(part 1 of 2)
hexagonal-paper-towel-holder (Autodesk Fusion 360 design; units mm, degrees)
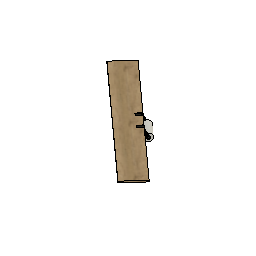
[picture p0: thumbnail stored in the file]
sketch "Sketch1" plane through (0, 0, 0) normal (0, 0, 1) x axis (1, 0, 0)
  line L1 (37.5278, 105) -> (-17.3205, 10)
  line L2 (90, 10) -> (-17.3205, 10)
  line L3 (117.5278, 105) -> (37.5278, 105)
  line L4 (15.1099, -13.1031) -> (117.5278, 105)
  line L5 (44.2265, 70) -> (47.1132, 75)
  line L6 (47.1132, 65) -> (44.2265, 70)
  line L7 (52.8868, 65) -> (47.1132, 65)
  line L8 (55.7735, 70) -> (52.8868, 65)
  line L9 (52.8868, 75) -> (55.7735, 70)
  line L10 (47.1132, 75) -> (52.8868, 75)
  line L11 (54.3301, 72.5) -> (50, 70)
  line L12 (54.3301, 67.5) -> (50, 70)
  line L13 (-19.6944, 13.5714) -> (-22.5812, 18.5714)
  line L14 (-13.9209, 13.5714) -> (-19.6944, 13.5714)
  line L15 (-11.0342, 18.5714) -> (-13.9209, 13.5714)
  line L16 (-13.9209, 23.5714) -> (-11.0342, 18.5714)
  line L17 (-22.5812, 18.5714) -> (-19.6944, 23.5714)
  line L18 (-19.6944, 23.5714) -> (-13.9209, 23.5714)
  line L19 (-8.5598, 20) -> (-11.4466, 25)
  line L20 (-2.7863, 20) -> (-8.5598, 20)
  line L21 (0.1004, 25) -> (-2.7863, 20)
  line L22 (-2.7863, 30) -> (0.1004, 25)
  line L23 (-11.4466, 25) -> (-8.5598, 30)
  line L24 (-8.5598, 30) -> (-2.7863, 30)
  line L25 (2.5748, 13.5714) -> (-0.312, 18.5714)
  line L26 (8.3483, 13.5714) -> (2.5748, 13.5714)
  line L27 (11.2351, 18.5714) -> (8.3483, 13.5714)
  line L28 (8.3483, 23.5714) -> (11.2351, 18.5714)
  line L29 (-0.312, 18.5714) -> (2.5748, 23.5714)
  line L30 (2.5748, 23.5714) -> (8.3483, 23.5714)
  line L31 (-8.5598, 32.8571) -> (-11.4466, 37.8571)
  line L32 (-2.7863, 32.8571) -> (-8.5598, 32.8571)
  line L33 (0.1004, 37.8571) -> (-2.7863, 32.8571)
  line L34 (-2.7863, 42.8571) -> (0.1004, 37.8571)
  line L35 (-11.4466, 37.8571) -> (-8.5598, 42.8571)
  line L36 (-8.5598, 42.8571) -> (-2.7863, 42.8571)
  line L37 (2.5748, 26.4286) -> (-0.312, 31.4286)
  line L38 (8.3483, 26.4286) -> (2.5748, 26.4286)
  line L39 (11.2351, 31.4286) -> (8.3483, 26.4286)
  line L40 (8.3483, 36.4286) -> (11.2351, 31.4286)
  line L41 (-0.312, 31.4286) -> (2.5748, 36.4286)
  line L42 (2.5748, 36.4286) -> (8.3483, 36.4286)
  line L43 (13.7094, 20) -> (10.8227, 25)
  line L44 (19.4829, 20) -> (13.7094, 20)
  line L45 (22.3697, 25) -> (19.4829, 20)
  line L46 (19.4829, 30) -> (22.3697, 25)
  line L47 (10.8227, 25) -> (13.7094, 30)
  line L48 (13.7094, 30) -> (19.4829, 30)
  line L49 (2.5748, 39.2857) -> (-0.312, 44.2857)
  line L50 (8.3483, 39.2857) -> (2.5748, 39.2857)
  line L51 (11.2351, 44.2857) -> (8.3483, 39.2857)
  line L52 (8.3483, 49.2857) -> (11.2351, 44.2857)
  line L53 (-0.312, 44.2857) -> (2.5748, 49.2857)
  line L54 (2.5748, 49.2857) -> (8.3483, 49.2857)
  line L55 (13.7094, 32.8571) -> (10.8227, 37.8571)
  line L56 (19.4829, 32.8571) -> (13.7094, 32.8571)
  line L57 (22.3697, 37.8571) -> (19.4829, 32.8571)
  line L58 (19.4829, 42.8571) -> (22.3697, 37.8571)
  line L59 (10.8227, 37.8571) -> (13.7094, 42.8571)
  line L60 (13.7094, 42.8571) -> (19.4829, 42.8571)
  line L61 (24.844, 26.4286) -> (21.9573, 31.4286)
  line L62 (30.6175, 26.4286) -> (24.844, 26.4286)
  line L63 (33.5043, 31.4286) -> (30.6175, 26.4286)
  line L64 (30.6175, 36.4286) -> (33.5043, 31.4286)
  line L65 (21.9573, 31.4286) -> (24.844, 36.4286)
  line L66 (24.844, 36.4286) -> (30.6175, 36.4286)
  line L67 (2.5748, 52.1429) -> (-0.312, 57.1429)
  line L68 (8.3483, 52.1429) -> (2.5748, 52.1429)
  line L69 (11.2351, 57.1429) -> (8.3483, 52.1429)
  line L70 (8.3483, 62.1429) -> (11.2351, 57.1429)
  line L71 (-0.312, 57.1429) -> (2.5748, 62.1429)
  line L72 (2.5748, 62.1429) -> (8.3483, 62.1429)
  line L73 (13.7094, 45.7143) -> (10.8227, 50.7143)
  line L74 (19.4829, 45.7143) -> (13.7094, 45.7143)
  line L75 (22.3697, 50.7143) -> (19.4829, 45.7143)
  line L76 (19.4829, 55.7143) -> (22.3697, 50.7143)
  line L77 (10.8227, 50.7143) -> (13.7094, 55.7143)
  line L78 (13.7094, 55.7143) -> (19.4829, 55.7143)
  line L79 (24.844, 39.2857) -> (21.9573, 44.2857)
  line L80 (30.6175, 39.2857) -> (24.844, 39.2857)
  line L81 (33.5043, 44.2857) -> (30.6175, 39.2857)
  line L82 (30.6175, 49.2857) -> (33.5043, 44.2857)
  line L83 (21.9573, 44.2857) -> (24.844, 49.2857)
  line L84 (24.844, 49.2857) -> (30.6175, 49.2857)
  line L85 (35.9786, 32.8571) -> (33.0919, 37.8571)
  line L86 (41.7521, 32.8571) -> (35.9786, 32.8571)
  line L87 (44.6389, 37.8571) -> (41.7521, 32.8571)
  line L88 (41.7521, 42.8571) -> (44.6389, 37.8571)
  line L89 (33.0919, 37.8571) -> (35.9786, 42.8571)
  line L90 (35.9786, 42.8571) -> (41.7521, 42.8571)
  line L91 (13.7094, 58.5714) -> (10.8227, 63.5714)
  line L92 (19.4829, 58.5714) -> (13.7094, 58.5714)
  line L93 (22.3697, 63.5714) -> (19.4829, 58.5714)
  line L94 (19.4829, 68.5714) -> (22.3697, 63.5714)
  line L95 (10.8227, 63.5714) -> (13.7094, 68.5714)
  line L96 (13.7094, 68.5714) -> (19.4829, 68.5714)
  line L97 (24.844, 52.1429) -> (21.9573, 57.1429)
  line L98 (30.6175, 52.1429) -> (24.844, 52.1429)
  line L99 (33.5043, 57.1429) -> (30.6175, 52.1429)
  line L100 (30.6175, 62.1429) -> (33.5043, 57.1429)
  line L101 (21.9573, 57.1429) -> (24.844, 62.1429)
  line L102 (24.844, 62.1429) -> (30.6175, 62.1429)
  line L103 (35.9786, 45.7143) -> (33.0919, 50.7143)
  line L104 (41.7521, 45.7143) -> (35.9786, 45.7143)
  line L105 (44.6389, 50.7143) -> (41.7521, 45.7143)
  line L106 (41.7521, 55.7143) -> (44.6389, 50.7143)
  line L107 (33.0919, 50.7143) -> (35.9786, 55.7143)
  line L108 (35.9786, 55.7143) -> (41.7521, 55.7143)
  line L109 (47.1132, 39.2857) -> (44.2265, 44.2857)
  line L110 (52.8868, 39.2857) -> (47.1132, 39.2857)
  line L111 (55.7735, 44.2857) -> (52.8868, 39.2857)
  line L112 (52.8868, 49.2857) -> (55.7735, 44.2857)
  line L113 (44.2265, 44.2857) -> (47.1132, 49.2857)
  line L114 (47.1132, 49.2857) -> (52.8868, 49.2857)
  line L115 (13.7094, 71.4286) -> (10.8227, 76.4286)
  line L116 (19.4829, 71.4286) -> (13.7094, 71.4286)
  line L117 (22.3697, 76.4286) -> (19.4829, 71.4286)
  line L118 (19.4829, 81.4286) -> (22.3697, 76.4286)
  line L119 (10.8227, 76.4286) -> (13.7094, 81.4286)
  line L120 (13.7094, 81.4286) -> (19.4829, 81.4286)
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  point P1 (0, 0)
  point P2 (0, 0)
  point P8 (50, 70)
  point P15 (50, 70)
  point P16 (50, 70)
  point P17 (54.3301, 72.5)
  point P18 (50, 70)
  point P19 (54.3301, 67.5)
  point P384 (0, 0)
  point P5 (37.5278, 105)
  point P6 (117.5278, 105)
  coincident P1 P2
  horizontal L2
  coincident P8 P15
  coincident P15 P16
  midpoint L9 P17
  coincident P8 P18
  midpoint L8 P19
  coincident P1 P384
  dimension "d1" diameter = 40
  dimension "d2" angle L1 L2 = 60
  dimension "d4" distance P5 P6 = 80
  dimension "d6" distance P15 L10 = 5
  dimension "d11" = 3
  dimension "d12" distance = 13
  dimension "d9" R-Pattern1-uDistance = 90
  dimension "d10" R-Pattern1-vDistance = 90
extrude "Extrude1" new body sketch "Sketch1" along normal blind 5
sketch "Sketch2" plane through (0, 0, 5) normal (0, 0, 1) x axis (-1, 0, 0)
  line L1 (-30.6175, -23.5714) -> (-24.844, -23.5714)
  line L2 (-33.5043, -18.5714) -> (-30.6175, -23.5714)
  line L3 (-30.6175, -13.5714) -> (-33.5043, -18.5714)
  line L4 (-24.844, -13.5714) -> (-30.6175, -13.5714)
  line L5 (-21.9573, -18.5714) -> (-24.844, -13.5714)
  line L6 (-24.844, -23.5714) -> (-21.9573, -18.5714)
  line L7 (-97.4252, -100.7143) -> (-91.6517, -100.7143)
  line L8 (-100.312, -95.7143) -> (-97.4252, -100.7143)
  line L9 (-97.4252, -90.7143) -> (-100.312, -95.7143)
  line L10 (-91.6517, -90.7143) -> (-97.4252, -90.7143)
  line L11 (-88.7649, -95.7143) -> (-91.6517, -90.7143)
  line L12 (-91.6517, -100.7143) -> (-88.7649, -95.7143)
  line L13 (-36.4555, -97.1429) -> (-41.7521, -97.1429)
  line L14 (-39.2598, -102) -> (-36.4555, -97.1429)
  line L15 (-44.5564, -102) -> (-39.2598, -102)
  line L16 (-41.7521, -97.1429) -> (-44.5564, -102)
  line L17 (-55.4436, -102) -> (-58.2479, -97.1429)
  line L18 (-66.8256, -102) -> (-55.4436, -102)
  line L19 (-64.0214, -97.1429) -> (-66.8256, -102)
  line L20 (-58.2479, -97.1429) -> (-64.0214, -97.1429)
  line L21 (-77.7128, -102) -> (-80.5171, -97.1429)
  line L22 (-89.0949, -102) -> (-77.7128, -102)
  line L23 (-86.2906, -97.1429) -> (-89.0949, -102)
  line L24 (-80.5171, -97.1429) -> (-86.2906, -97.1429)
  line L25 (-99.982, -102) -> (-102.7863, -97.1429)
  line L26 (-110.9553, -102) -> (-99.982, -102)
  line L27 (-106.7432, -97.1429) -> (-110.9553, -102)
  line L28 (-102.7863, -97.1429) -> (-106.7432, -97.1429)
  line L29 (-104.2655, -94.2857) -> (-102.7863, -94.2857)
  line L30 (-99.9116, -89.2649) -> (-104.2655, -94.2857)
  line L31 (-99.8996, -89.2857) -> (-99.9116, -89.2649)
  line L32 (-102.7863, -94.2857) -> (-99.8996, -89.2857)
  line L33 (-97.931, -86.9811) -> (-97.4252, -87.8571)
  line L34 (-90.9991, -78.9875) -> (-97.931, -86.9811)
  line L35 (-88.7649, -82.8571) -> (-90.9991, -78.9875)
  line L36 (-91.6517, -87.8571) -> (-88.7649, -82.8571)
  line L37 (-97.4252, -87.8571) -> (-91.6517, -87.8571)
  line L38 (-89.0185, -76.7036) -> (-86.2906, -81.4286)
  line L39 (-84.444, -71.4286) -> (-89.0185, -76.7036)
  line L40 (-80.5171, -71.4286) -> (-84.444, -71.4286)
  line L41 (-77.6303, -76.4286) -> (-80.5171, -71.4286)
  line L42 (-80.5171, -81.4286) -> (-77.6303, -76.4286)
  line L43 (-86.2906, -81.4286) -> (-80.5171, -81.4286)
  line L44 (-25.3209, -77.8571) -> (-30.6175, -77.8571)
  line L45 (-30.856, -87.4441) -> (-25.3209, -77.8571)
  line L46 (-33.5043, -82.8571) -> (-30.856, -87.4441)
  line L47 (-30.6175, -77.8571) -> (-33.5043, -82.8571)
  line L48 (-14.1863, -58.5714) -> (-19.4829, -58.5714)
  line L49 (-19.7214, -68.1584) -> (-14.1863, -58.5714)
  line L50 (-22.3697, -63.5714) -> (-19.7214, -68.1584)
  line L51 (-19.4829, -58.5714) -> (-22.3697, -63.5714)
  line L52 (-86.2906, -94.2857) -> (-80.5171, -94.2857)
  line L53 (-89.1773, -89.2857) -> (-86.2906, -94.2857)
  line L54 (-86.2906, -84.2857) -> (-89.1773, -89.2857)
  line L55 (-80.5171, -84.2857) -> (-86.2906, -84.2857)
  line L56 (-77.6303, -89.2857) -> (-80.5171, -84.2857)
  line L57 (-80.5171, -94.2857) -> (-77.6303, -89.2857)
  line L58 (-75.156, -100.7143) -> (-69.3825, -100.7143)
  line L59 (-78.0427, -95.7143) -> (-75.156, -100.7143)
  line L60 (-75.156, -90.7143) -> (-78.0427, -95.7143)
  line L61 (-69.3825, -90.7143) -> (-75.156, -90.7143)
  line L62 (-66.4957, -95.7143) -> (-69.3825, -90.7143)
  line L63 (-69.3825, -100.7143) -> (-66.4957, -95.7143)
  line L64 (-75.156, -87.8571) -> (-69.3825, -87.8571)
  line L65 (-78.0427, -82.8571) -> (-75.156, -87.8571)
  line L66 (-75.156, -77.8571) -> (-78.0427, -82.8571)
  line L67 (-69.3825, -77.8571) -> (-75.156, -77.8571)
  line L68 (-66.4957, -82.8571) -> (-69.3825, -77.8571)
  line L69 (-69.3825, -87.8571) -> (-66.4957, -82.8571)
  line L70 (-64.0214, -94.2857) -> (-58.2479, -94.2857)
  line L71 (-66.9081, -89.2857) -> (-64.0214, -94.2857)
  line L72 (-64.0214, -84.2857) -> (-66.9081, -89.2857)
  line L73 (-58.2479, -84.2857) -> (-64.0214, -84.2857)
  line L74 (-55.3611, -89.2857) -> (-58.2479, -84.2857)
  line L75 (-58.2479, -94.2857) -> (-55.3611, -89.2857)
  line L76 (-52.8868, -100.7143) -> (-47.1132, -100.7143)
  line L77 (-55.7735, -95.7143) -> (-52.8868, -100.7143)
  line L78 (-52.8868, -90.7143) -> (-55.7735, -95.7143)
  line L79 (-47.1132, -90.7143) -> (-52.8868, -90.7143)
  line L80 (-44.2265, -95.7143) -> (-47.1132, -90.7143)
  line L81 (-47.1132, -100.7143) -> (-44.2265, -95.7143)
  line L82 (-75.156, -75) -> (-69.3825, -75)
  line L83 (-78.0427, -70) -> (-75.156, -75)
  line L84 (-75.156, -65) -> (-78.0427, -70)
  line L85 (-69.3825, -65) -> (-75.156, -65)
  line L86 (-66.4957, -70) -> (-69.3825, -65)
  line L87 (-69.3825, -75) -> (-66.4957, -70)
  line L88 (-64.0214, -81.4286) -> (-58.2479, -81.4286)
  line L89 (-66.9081, -76.4286) -> (-64.0214, -81.4286)
  line L90 (-64.0214, -71.4286) -> (-66.9081, -76.4286)
  line L91 (-58.2479, -71.4286) -> (-64.0214, -71.4286)
  line L92 (-55.3611, -76.4286) -> (-58.2479, -71.4286)
  line L93 (-58.2479, -81.4286) -> (-55.3611, -76.4286)
  line L94 (-52.8868, -87.8571) -> (-47.1132, -87.8571)
  line L95 (-55.7735, -82.8571) -> (-52.8868, -87.8571)
  line L96 (-52.8868, -77.8571) -> (-55.7735, -82.8571)
  line L97 (-47.1132, -77.8571) -> (-52.8868, -77.8571)
  line L98 (-44.2265, -82.8571) -> (-47.1132, -77.8571)
  line L99 (-47.1132, -87.8571) -> (-44.2265, -82.8571)
  line L100 (-41.7521, -94.2857) -> (-35.9786, -94.2857)
  line L101 (-44.6389, -89.2857) -> (-41.7521, -94.2857)
  line L102 (-41.7521, -84.2857) -> (-44.6389, -89.2857)
  line L103 (-35.9786, -84.2857) -> (-41.7521, -84.2857)
  line L104 (-33.0919, -89.2857) -> (-35.9786, -84.2857)
  line L105 (-35.9786, -94.2857) -> (-33.0919, -89.2857)
  line L106 (-64.0214, -68.5714) -> (-58.2479, -68.5714)
  line L107 (-66.9081, -63.5714) -> (-64.0214, -68.5714)
  line L108 (-64.0214, -58.5714) -> (-66.9081, -63.5714)
  line L109 (-58.2479, -58.5714) -> (-64.0214, -58.5714)
  line L110 (-55.3611, -63.5714) -> (-58.2479, -58.5714)
  line L111 (-58.2479, -68.5714) -> (-55.3611, -63.5714)
  line L112 (-41.7521, -81.4286) -> (-35.9786, -81.4286)
  line L113 (-44.6389, -76.4286) -> (-41.7521, -81.4286)
  line L114 (-41.7521, -71.4286) -> (-44.6389, -76.4286)
  line L115 (-35.9786, -71.4286) -> (-41.7521, -71.4286)
  line L116 (-33.0919, -76.4286) -> (-35.9786, -71.4286)
  line L117 (-35.9786, -81.4286) -> (-33.0919, -76.4286)
  line L118 (-52.8868, -62.1429) -> (-47.1132, -62.1429)
  line L119 (-55.7735, -57.1429) -> (-52.8868, -62.1429)
  line L120 (-52.8868, -52.1429) -> (-55.7735, -57.1429)
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  point P28 (-110.9553, -102)
  point P274 (-110.9553, -102)
  coincident P28 P274
extrude "Extrude2" add sketch "Sketch2" along normal blind 17
extrude "Extrude3" add sketch "Sketch2" along normal blind 10
sketch "Sketch3" plane through (-17.3205, 10, 0) normal (-0.866, 0.5, 0) x axis (-0.5, -0.866, 0)
  line L1 (0, 0) -> (-109.6966, 0)
  line L2 (0, 5) -> (0, 0)
  line L3 (-106.2324, 5) -> (0, 5)
  line L4 (-106.2324, 15) -> (-106.2324, 5)
  line L5 (-109.6966, 15) -> (-106.2324, 15)
  line L6 (-109.6966, 0) -> (-109.6966, 15)
  line L7 (-95.8985, 4.666) -> (-106.2324, 15)
  line L8 (-91.618, 15) -> (-106.2324, 15)
  line L9 (-95.8985, 0) -> (-95.8985, 4.666)
  point P6 (-106.2324, 15)
  point P8 (-106.2324, 15)
  point P11 (-95.8985, 0)
  horizontal L8
  coincident P6 P8
  coincident L1 P11
  perpendicular L1 L9
  dimension "d19" angle L7 L8 = 45
extrude "Extrude4" add sketch "Sketch3" profile of L1 L3 L4 L5 L6 L7 L9 against normal blind 3
sketch "Sketch4" plane through (15.1099, -13.1031, 0) normal (0.7555, -0.6552, 0) x axis (0.6552, 0.7555, 0)
  line L1 (156.3259, 0) -> (0, 0)
  line L2 (156.3259, 15) -> (156.3259, 0)
  line L3 (152.3549, 15) -> (156.3259, 15)
  line L4 (152.3549, 5) -> (152.3549, 15)
  line L5 (0, 5) -> (152.3549, 5)
  line L6 (0, 0) -> (0, 5)
  line L7 (140.8509, 3.496) -> (152.3549, 15)
  line L8 (168.6241, 15) -> (152.3549, 15)
  line L9 (140.8509, 0) -> (140.8509, 3.496)
  point P5 (152.3549, 15)
  point P8 (152.3549, 15)
  horizontal L8
  coincident P5 P8
  vertical L9
  dimension "d22" angle L7 L8 = 135
extrude "Extrude5" add sketch "Sketch4" profile of L1 L2 L3 L4 L5 L7 L9 against normal blind 3
split "Split1"
remove_body "RemoveBody1"
sketch "Sketch1" plane through (0, 0, 0) normal (0, 0, 1) x axis (1, 0, 0)
  line L1 (7.5056, -13) -> (15.0111, 0)
  line L2 (-7.5056, -13) -> (7.5056, -13)
  line L3 (-15.0111, 0) -> (-7.5056, -13)
  line L4 (-7.5056, 13) -> (-15.0111, 0)
  line L5 (7.5056, 13) -> (-7.5056, 13)
  line L6 (15.0111, 0) -> (7.5056, 13)
  line L7 (-14.4338, 0) -> (-7.2169, -12.5)
  line L8 (-7.2169, 12.5) -> (-14.4338, 0)
  line L9 (7.2169, 12.5) -> (-7.2169, 12.5)
  line L10 (14.4338, 0) -> (7.2169, 12.5)
  line L11 (7.2169, -12.5) -> (14.4338, 0)
  line L12 (-7.2169, -12.5) -> (7.2169, -12.5)
  dimension "d32" = 0.5
extrude "Extrude1" new body sketch "Sketch1" profile of L7 L8 L9 L10 L11 L12 along normal blind 50
sketch "Sketch2" plane through (0, 0, 0) normal (0, 0, -1) x axis (1, 0, 0)
  line L1 (7.2169, 12.5) -> (14.4338, 0)
  line L2 (-7.2169, 12.5) -> (7.2169, 12.5)
  line L3 (-14.4338, 0) -> (-7.2169, 12.5)
  line L4 (-7.2169, -12.5) -> (-14.4338, 0)
  line L5 (7.2169, -12.5) -> (-7.2169, -12.5)
  line L6 (14.4338, 0) -> (7.2169, -12.5)
  circle C1 centre (0, 0) radius 20
  point P1 (0, 0)
  point P8 (0, 0)
  coincident P1 P8
  dimension "d35" diameter C1 = 40
extrude "Extrude2" add sketch "Sketch2" along normal blind 2
move "Move1"
move "Move2"
move "Move3"
move "Move4"
sketch "Sketch1" plane through (0, 0, 0) normal (0, 0, 1) x axis (1, 0, 0)
  line L1 (37.5278, 105) -> (-17.3205, 10)
  line L2 (90, 10) -> (-17.3205, 10)
  line L3 (117.5278, 105) -> (37.5278, 105)
  line L4 (15.1099, -13.1031) -> (117.5278, 105)
  line L5 (44.2265, 70) -> (47.1132, 75)
  line L6 (47.1132, 65) -> (44.2265, 70)
  line L7 (52.8868, 65) -> (47.1132, 65)
  line L8 (55.7735, 70) -> (52.8868, 65)
  line L9 (52.8868, 75) -> (55.7735, 70)
  line L10 (47.1132, 75) -> (52.8868, 75)
  line L11 (54.3301, 72.5) -> (50, 70)
  line L12 (54.3301, 67.5) -> (50, 70)
  line L13 (-19.6944, 13.5714) -> (-22.5812, 18.5714)
  line L14 (-13.9209, 13.5714) -> (-19.6944, 13.5714)
  line L15 (-11.0342, 18.5714) -> (-13.9209, 13.5714)
  line L16 (-13.9209, 23.5714) -> (-11.0342, 18.5714)
  line L17 (-22.5812, 18.5714) -> (-19.6944, 23.5714)
  line L18 (-19.6944, 23.5714) -> (-13.9209, 23.5714)
  line L19 (-8.5598, 20) -> (-11.4466, 25)
  line L20 (-2.7863, 20) -> (-8.5598, 20)
  line L21 (0.1004, 25) -> (-2.7863, 20)
  line L22 (-2.7863, 30) -> (0.1004, 25)
  line L23 (-11.4466, 25) -> (-8.5598, 30)
  line L24 (-8.5598, 30) -> (-2.7863, 30)
  line L25 (2.5748, 13.5714) -> (-0.312, 18.5714)
  line L26 (8.3483, 13.5714) -> (2.5748, 13.5714)
  line L27 (11.2351, 18.5714) -> (8.3483, 13.5714)
  line L28 (8.3483, 23.5714) -> (11.2351, 18.5714)
  line L29 (-0.312, 18.5714) -> (2.5748, 23.5714)
  line L30 (2.5748, 23.5714) -> (8.3483, 23.5714)
  line L31 (-8.5598, 32.8571) -> (-11.4466, 37.8571)
  line L32 (-2.7863, 32.8571) -> (-8.5598, 32.8571)
  line L33 (0.1004, 37.8571) -> (-2.7863, 32.8571)
  line L34 (-2.7863, 42.8571) -> (0.1004, 37.8571)
  line L35 (-11.4466, 37.8571) -> (-8.5598, 42.8571)
  line L36 (-8.5598, 42.8571) -> (-2.7863, 42.8571)
  line L37 (2.5748, 26.4286) -> (-0.312, 31.4286)
  line L38 (8.3483, 26.4286) -> (2.5748, 26.4286)
  line L39 (11.2351, 31.4286) -> (8.3483, 26.4286)
  line L40 (8.3483, 36.4286) -> (11.2351, 31.4286)
  line L41 (-0.312, 31.4286) -> (2.5748, 36.4286)
  line L42 (2.5748, 36.4286) -> (8.3483, 36.4286)
  line L43 (13.7094, 20) -> (10.8227, 25)
  line L44 (19.4829, 20) -> (13.7094, 20)
  line L45 (22.3697, 25) -> (19.4829, 20)
  line L46 (19.4829, 30) -> (22.3697, 25)
  line L47 (10.8227, 25) -> (13.7094, 30)
  line L48 (13.7094, 30) -> (19.4829, 30)
  line L49 (2.5748, 39.2857) -> (-0.312, 44.2857)
  line L50 (8.3483, 39.2857) -> (2.5748, 39.2857)
  line L51 (11.2351, 44.2857) -> (8.3483, 39.2857)
  line L52 (8.3483, 49.2857) -> (11.2351, 44.2857)
  line L53 (-0.312, 44.2857) -> (2.5748, 49.2857)
  line L54 (2.5748, 49.2857) -> (8.3483, 49.2857)
  line L55 (13.7094, 32.8571) -> (10.8227, 37.8571)
  line L56 (19.4829, 32.8571) -> (13.7094, 32.8571)
  line L57 (22.3697, 37.8571) -> (19.4829, 32.8571)
  line L58 (19.4829, 42.8571) -> (22.3697, 37.8571)
  line L59 (10.8227, 37.8571) -> (13.7094, 42.8571)
  line L60 (13.7094, 42.8571) -> (19.4829, 42.8571)
  line L61 (24.844, 26.4286) -> (21.9573, 31.4286)
  line L62 (30.6175, 26.4286) -> (24.844, 26.4286)
  line L63 (33.5043, 31.4286) -> (30.6175, 26.4286)
  line L64 (30.6175, 36.4286) -> (33.5043, 31.4286)
  line L65 (21.9573, 31.4286) -> (24.844, 36.4286)
  line L66 (24.844, 36.4286) -> (30.6175, 36.4286)
  line L67 (2.5748, 52.1429) -> (-0.312, 57.1429)
  line L68 (8.3483, 52.1429) -> (2.5748, 52.1429)
  line L69 (11.2351, 57.1429) -> (8.3483, 52.1429)
  line L70 (8.3483, 62.1429) -> (11.2351, 57.1429)
  line L71 (-0.312, 57.1429) -> (2.5748, 62.1429)
  line L72 (2.5748, 62.1429) -> (8.3483, 62.1429)
  line L73 (13.7094, 45.7143) -> (10.8227, 50.7143)
  line L74 (19.4829, 45.7143) -> (13.7094, 45.7143)
  line L75 (22.3697, 50.7143) -> (19.4829, 45.7143)
  line L76 (19.4829, 55.7143) -> (22.3697, 50.7143)
  line L77 (10.8227, 50.7143) -> (13.7094, 55.7143)
  line L78 (13.7094, 55.7143) -> (19.4829, 55.7143)
  line L79 (24.844, 39.2857) -> (21.9573, 44.2857)
  line L80 (30.6175, 39.2857) -> (24.844, 39.2857)
  line L81 (33.5043, 44.2857) -> (30.6175, 39.2857)
  line L82 (30.6175, 49.2857) -> (33.5043, 44.2857)
  line L83 (21.9573, 44.2857) -> (24.844, 49.2857)
  line L84 (24.844, 49.2857) -> (30.6175, 49.2857)
  line L85 (35.9786, 32.8571) -> (33.0919, 37.8571)
  line L86 (41.7521, 32.8571) -> (35.9786, 32.8571)
  line L87 (44.6389, 37.8571) -> (41.7521, 32.8571)
  line L88 (41.7521, 42.8571) -> (44.6389, 37.8571)
  line L89 (33.0919, 37.8571) -> (35.9786, 42.8571)
  line L90 (35.9786, 42.8571) -> (41.7521, 42.8571)
  line L91 (13.7094, 58.5714) -> (10.8227, 63.5714)
  line L92 (19.4829, 58.5714) -> (13.7094, 58.5714)
  line L93 (22.3697, 63.5714) -> (19.4829, 58.5714)
  line L94 (19.4829, 68.5714) -> (22.3697, 63.5714)
  line L95 (10.8227, 63.5714) -> (13.7094, 68.5714)
  line L96 (13.7094, 68.5714) -> (19.4829, 68.5714)
  line L97 (24.844, 52.1429) -> (21.9573, 57.1429)
  line L98 (30.6175, 52.1429) -> (24.844, 52.1429)
  line L99 (33.5043, 57.1429) -> (30.6175, 52.1429)
  line L100 (30.6175, 62.1429) -> (33.5043, 57.1429)
  line L101 (21.9573, 57.1429) -> (24.844, 62.1429)
  line L102 (24.844, 62.1429) -> (30.6175, 62.1429)
  line L103 (35.9786, 45.7143) -> (33.0919, 50.7143)
  line L104 (41.7521, 45.7143) -> (35.9786, 45.7143)
  line L105 (44.6389, 50.7143) -> (41.7521, 45.7143)
  line L106 (41.7521, 55.7143) -> (44.6389, 50.7143)
  line L107 (33.0919, 50.7143) -> (35.9786, 55.7143)
  line L108 (35.9786, 55.7143) -> (41.7521, 55.7143)
  line L109 (47.1132, 39.2857) -> (44.2265, 44.2857)
  line L110 (52.8868, 39.2857) -> (47.1132, 39.2857)
  line L111 (55.7735, 44.2857) -> (52.8868, 39.2857)
  line L112 (52.8868, 49.2857) -> (55.7735, 44.2857)
  line L113 (44.2265, 44.2857) -> (47.1132, 49.2857)
  line L114 (47.1132, 49.2857) -> (52.8868, 49.2857)
  line L115 (13.7094, 71.4286) -> (10.8227, 76.4286)
  line L116 (19.4829, 71.4286) -> (13.7094, 71.4286)
  line L117 (22.3697, 76.4286) -> (19.4829, 71.4286)
  line L118 (19.4829, 81.4286) -> (22.3697, 76.4286)
  line L119 (10.8227, 76.4286) -> (13.7094, 81.4286)
  line L120 (13.7094, 81.4286) -> (19.4829, 81.4286)
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  point P1 (0, 0)
  point P2 (0, 0)
  point P8 (50, 70)
  point P15 (50, 70)
  point P16 (50, 70)
  point P17 (54.3301, 72.5)
  point P18 (50, 70)
  point P19 (54.3301, 67.5)
  point P384 (0, 0)
  point P5 (37.5278, 105)
  point P6 (117.5278, 105)
  coincident P1 P2
  horizontal L2
  coincident P8 P15
  coincident P15 P16
  midpoint L9 P17
  coincident P8 P18
  midpoint L8 P19
  coincident P1 P384
  dimension "d1_1" diameter = 40
  dimension "d2_1" angle L1 L2 = 60
  dimension "d4_1" distance P5 P6 = 80
  dimension "d6_1" distance P15 L10 = 5
  dimension "d11_1" = 3
  dimension "d12_1" distance = 13
  dimension "d9_1" R-Pattern1-uDistance = 90
  dimension "d10_1" R-Pattern1-vDistance = 90
extrude "Extrude1" new body sketch "Sketch1" along normal blind 5 named "d13_1"
sketch "Sketch2" plane through (0, 0, 5) normal (0, 0, 1) x axis (-1, 0, 0)
  line L1 (-30.6175, -23.5714) -> (-24.844, -23.5714)
  line L2 (-33.5043, -18.5714) -> (-30.6175, -23.5714)
  line L3 (-30.6175, -13.5714) -> (-33.5043, -18.5714)
  line L4 (-24.844, -13.5714) -> (-30.6175, -13.5714)
  line L5 (-21.9573, -18.5714) -> (-24.844, -13.5714)
  line L6 (-24.844, -23.5714) -> (-21.9573, -18.5714)
  line L7 (-97.4252, -100.7143) -> (-91.6517, -100.7143)
  line L8 (-100.312, -95.7143) -> (-97.4252, -100.7143)
  line L9 (-97.4252, -90.7143) -> (-100.312, -95.7143)
  line L10 (-91.6517, -90.7143) -> (-97.4252, -90.7143)
  line L11 (-88.7649, -95.7143) -> (-91.6517, -90.7143)
  line L12 (-91.6517, -100.7143) -> (-88.7649, -95.7143)
  line L13 (-36.4555, -97.1429) -> (-41.7521, -97.1429)
  line L14 (-39.2598, -102) -> (-36.4555, -97.1429)
  line L15 (-44.5564, -102) -> (-39.2598, -102)
  line L16 (-41.7521, -97.1429) -> (-44.5564, -102)
  line L17 (-55.4436, -102) -> (-58.2479, -97.1429)
  line L18 (-66.8256, -102) -> (-55.4436, -102)
  line L19 (-64.0214, -97.1429) -> (-66.8256, -102)
  line L20 (-58.2479, -97.1429) -> (-64.0214, -97.1429)
  line L21 (-77.7128, -102) -> (-80.5171, -97.1429)
  line L22 (-89.0949, -102) -> (-77.7128, -102)
  line L23 (-86.2906, -97.1429) -> (-89.0949, -102)
  line L24 (-80.5171, -97.1429) -> (-86.2906, -97.1429)
  line L25 (-99.982, -102) -> (-102.7863, -97.1429)
  line L26 (-110.9553, -102) -> (-99.982, -102)
  line L27 (-106.7432, -97.1429) -> (-110.9553, -102)
  line L28 (-102.7863, -97.1429) -> (-106.7432, -97.1429)
  line L29 (-104.2655, -94.2857) -> (-102.7863, -94.2857)
  line L30 (-99.9116, -89.2649) -> (-104.2655, -94.2857)
  line L31 (-99.8996, -89.2857) -> (-99.9116, -89.2649)
  line L32 (-102.7863, -94.2857) -> (-99.8996, -89.2857)
  line L33 (-97.931, -86.9811) -> (-97.4252, -87.8571)
  line L34 (-90.9991, -78.9875) -> (-97.931, -86.9811)
  line L35 (-88.7649, -82.8571) -> (-90.9991, -78.9875)
  line L36 (-91.6517, -87.8571) -> (-88.7649, -82.8571)
  line L37 (-97.4252, -87.8571) -> (-91.6517, -87.8571)
  line L38 (-89.0185, -76.7036) -> (-86.2906, -81.4286)
  line L39 (-84.444, -71.4286) -> (-89.0185, -76.7036)
  line L40 (-80.5171, -71.4286) -> (-84.444, -71.4286)
  line L41 (-77.6303, -76.4286) -> (-80.5171, -71.4286)
  line L42 (-80.5171, -81.4286) -> (-77.6303, -76.4286)
  line L43 (-86.2906, -81.4286) -> (-80.5171, -81.4286)
  line L44 (-25.3209, -77.8571) -> (-30.6175, -77.8571)
  line L45 (-30.856, -87.4441) -> (-25.3209, -77.8571)
  line L46 (-33.5043, -82.8571) -> (-30.856, -87.4441)
  line L47 (-30.6175, -77.8571) -> (-33.5043, -82.8571)
  line L48 (-14.1863, -58.5714) -> (-19.4829, -58.5714)
  line L49 (-19.7214, -68.1584) -> (-14.1863, -58.5714)
  line L50 (-22.3697, -63.5714) -> (-19.7214, -68.1584)
  line L51 (-19.4829, -58.5714) -> (-22.3697, -63.5714)
  line L52 (-86.2906, -94.2857) -> (-80.5171, -94.2857)
  line L53 (-89.1773, -89.2857) -> (-86.2906, -94.2857)
  line L54 (-86.2906, -84.2857) -> (-89.1773, -89.2857)
  line L55 (-80.5171, -84.2857) -> (-86.2906, -84.2857)
  line L56 (-77.6303, -89.2857) -> (-80.5171, -84.2857)
  line L57 (-80.5171, -94.2857) -> (-77.6303, -89.2857)
  line L58 (-75.156, -100.7143) -> (-69.3825, -100.7143)
  line L59 (-78.0427, -95.7143) -> (-75.156, -100.7143)
  line L60 (-75.156, -90.7143) -> (-78.0427, -95.7143)
  line L61 (-69.3825, -90.7143) -> (-75.156, -90.7143)
  line L62 (-66.4957, -95.7143) -> (-69.3825, -90.7143)
  line L63 (-69.3825, -100.7143) -> (-66.4957, -95.7143)
  line L64 (-75.156, -87.8571) -> (-69.3825, -87.8571)
  line L65 (-78.0427, -82.8571) -> (-75.156, -87.8571)
  line L66 (-75.156, -77.8571) -> (-78.0427, -82.8571)
  line L67 (-69.3825, -77.8571) -> (-75.156, -77.8571)
  line L68 (-66.4957, -82.8571) -> (-69.3825, -77.8571)
  line L69 (-69.3825, -87.8571) -> (-66.4957, -82.8571)
  line L70 (-64.0214, -94.2857) -> (-58.2479, -94.2857)
  line L71 (-66.9081, -89.2857) -> (-64.0214, -94.2857)
  line L72 (-64.0214, -84.2857) -> (-66.9081, -89.2857)
  line L73 (-58.2479, -84.2857) -> (-64.0214, -84.2857)
  line L74 (-55.3611, -89.2857) -> (-58.2479, -84.2857)
  line L75 (-58.2479, -94.2857) -> (-55.3611, -89.2857)
  line L76 (-52.8868, -100.7143) -> (-47.1132, -100.7143)
  line L77 (-55.7735, -95.7143) -> (-52.8868, -100.7143)
  line L78 (-52.8868, -90.7143) -> (-55.7735, -95.7143)
  line L79 (-47.1132, -90.7143) -> (-52.8868, -90.7143)
  line L80 (-44.2265, -95.7143) -> (-47.1132, -90.7143)
  line L81 (-47.1132, -100.7143) -> (-44.2265, -95.7143)
  line L82 (-75.156, -75) -> (-69.3825, -75)
  line L83 (-78.0427, -70) -> (-75.156, -75)
  line L84 (-75.156, -65) -> (-78.0427, -70)
  line L85 (-69.3825, -65) -> (-75.156, -65)
  line L86 (-66.4957, -70) -> (-69.3825, -65)
  line L87 (-69.3825, -75) -> (-66.4957, -70)
  line L88 (-64.0214, -81.4286) -> (-58.2479, -81.4286)
  line L89 (-66.9081, -76.4286) -> (-64.0214, -81.4286)
  line L90 (-64.0214, -71.4286) -> (-66.9081, -76.4286)
  line L91 (-58.2479, -71.4286) -> (-64.0214, -71.4286)
  line L92 (-55.3611, -76.4286) -> (-58.2479, -71.4286)
  line L93 (-58.2479, -81.4286) -> (-55.3611, -76.4286)
  line L94 (-52.8868, -87.8571) -> (-47.1132, -87.8571)
  line L95 (-55.7735, -82.8571) -> (-52.8868, -87.8571)
  line L96 (-52.8868, -77.8571) -> (-55.7735, -82.8571)
  line L97 (-47.1132, -77.8571) -> (-52.8868, -77.8571)
  line L98 (-44.2265, -82.8571) -> (-47.1132, -77.8571)
  line L99 (-47.1132, -87.8571) -> (-44.2265, -82.8571)
  line L100 (-41.7521, -94.2857) -> (-35.9786, -94.2857)
  line L101 (-44.6389, -89.2857) -> (-41.7521, -94.2857)
  line L102 (-41.7521, -84.2857) -> (-44.6389, -89.2857)
  line L103 (-35.9786, -84.2857) -> (-41.7521, -84.2857)
  line L104 (-33.0919, -89.2857) -> (-35.9786, -84.2857)
  line L105 (-35.9786, -94.2857) -> (-33.0919, -89.2857)
  line L106 (-64.0214, -68.5714) -> (-58.2479, -68.5714)
  line L107 (-66.9081, -63.5714) -> (-64.0214, -68.5714)
  line L108 (-64.0214, -58.5714) -> (-66.9081, -63.5714)
  line L109 (-58.2479, -58.5714) -> (-64.0214, -58.5714)
  line L110 (-55.3611, -63.5714) -> (-58.2479, -58.5714)
  line L111 (-58.2479, -68.5714) -> (-55.3611, -63.5714)
  line L112 (-41.7521, -81.4286) -> (-35.9786, -81.4286)
  line L113 (-44.6389, -76.4286) -> (-41.7521, -81.4286)
  line L114 (-41.7521, -71.4286) -> (-44.6389, -76.4286)
  line L115 (-35.9786, -71.4286) -> (-41.7521, -71.4286)
  line L116 (-33.0919, -76.4286) -> (-35.9786, -71.4286)
  line L117 (-35.9786, -81.4286) -> (-33.0919, -76.4286)
  line L118 (-52.8868, -62.1429) -> (-47.1132, -62.1429)
  line L119 (-55.7735, -57.1429) -> (-52.8868, -62.1429)
  line L120 (-52.8868, -52.1429) -> (-55.7735, -57.1429)
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  point P28 (-110.9553, -102)
  point P274 (-110.9553, -102)
  coincident P28 P274
extrude "Extrude2" add sketch "Sketch2" along normal blind 17 named "d15_1"
extrude "Extrude3" add sketch "Sketch2" along normal blind 30 named "d17_1"
sketch "Sketch3" plane through (-17.3205, 10, 0) normal (-0.866, 0.5, 0) x axis (-0.5, -0.866, 0)
  line L1 (0, 0) -> (-109.6966, 0)
  line L2 (0, 5) -> (0, 0)
  line L3 (-106.2324, 5) -> (0, 5)
  line L4 (-106.2324, 35) -> (-106.2324, 5)
  line L5 (-109.6966, 35) -> (-106.2324, 35)
  line L6 (-109.6966, 0) -> (-109.6966, 35)
  line L7 (-91.618, 35) -> (-106.2324, 35)
  line L8 (-94.1706, 0) -> (-109.6966, 0)
  line L9 (-106.2324, 35) -> (-94.1706, 0)
  point P6 (-106.2324, 35)
  point P8 (-106.2324, 35)
  point P10 (-94.1706, 0)
  point P2 (-109.6966, 0)
  point P11 (-109.6966, 0)
  point P12 (-106.2324, 35)
  horizontal L7
  coincident P6 P8
  coincident L1 P10
  coincident P2 P11
  coincident P6 P12
  dimension "d73" distance P10 P11 = 15.526
extrude "Extrude4" add sketch "Sketch3" profile of L1 L3 L4 L5 L6 against normal blind 3 named "d20_1"
sketch "Sketch4" plane through (15.1099, -13.1031, 0) normal (0.7555, -0.6552, 0) x axis (0.6552, 0.7555, 0)
  line L1 (156.3259, 0) -> (0, 0)
  line L2 (156.3259, 35) -> (156.3259, 0)
  line L3 (152.3549, 35) -> (156.3259, 35)
  line L4 (152.3549, 5) -> (152.3549, 35)
  line L5 (0, 5) -> (152.3549, 5)
  line L6 (0, 0) -> (0, 5)
  line L7 (168.6241, 35) -> (152.3549, 35)
  line L8 (140.7999, 0) -> (156.3259, 0)
  line L9 (152.3549, 35) -> (140.7999, 0)
  point P5 (152.3549, 35)
  point P8 (152.3549, 35)
  point P3 (156.3259, 0)
  point P10 (156.3259, 0)
  point P11 (140.7999, 0)
  horizontal L7
  coincident P5 P8
  coincident P3 P10
  perpendicular L2 L8
  dimension "d74" distance P10 P11 = 15.526
extrude "Extrude5" add sketch "Sketch4" profile of L4 L5 L9 against normal blind 3 named "d23_1"
move "Move1"
move "Move2"
move "Move3"
move "Move4"
mirror "Mirror1" mirrorStitchTolerance 0.1
sketch "Sketch1" plane through (0, 0, 0) normal (0, 1, 0) x axis (1, 0, 0)
  circle C1 centre (0, 0) radius 22.5
  circle C2 centre (0, 0) radius 50
  circle C3 centre (0, 0) radius 23.5
  point P1 (0, 0)
  point P2 (0, 0)
  point P3 (0, 0)
  coincident P1 P2
  coincident P1 P3
  concentric C1 C3
  dimension "d40" diameter C1 = 45
  dimension "d41" diameter C2 = 100
  dimension "d44" diameter C3 = 47
extrude "Extrude1" new body sketch "Sketch1" distance 110
move "Move1"
position "Position1"
position "Position2"
sketch "Sketch3" plane through (-10.8253, 6.25, 0) normal (-0.866, 0.5, 0) x axis (-0.5, -0.866, 0)
  line L1 (7.2169, 0) -> (-7.2169, 0)
  line L2 (7.2169, 50) -> (7.2169, 0)
  line L3 (-7.2169, 50) -> (7.2169, 50)
  line L4 (-7.2169, 0) -> (-7.2169, 50)
sketch "Sketch4" plane through (0, -12.5, 0) normal (0, -1, 0) x axis (1, 0, 0)
  line L1 (7.2169, 0) -> (-7.2169, 0)
  line L2 (7.2169, 50) -> (7.2169, 0)
  line L3 (-7.2169, 50) -> (7.2169, 50)
  line L4 (-7.2169, 0) -> (-7.2169, 50)
  line L5 (-52.9297, -27.3333) -> (-52.9297, 78.5)
  line L6 (52.9037, -27.3333) -> (-52.9297, -27.3333)
  line L7 (52.9037, 78.5) -> (52.9037, -27.3333)
  line L8 (-52.9297, 78.5) -> (52.9037, 78.5)
  line L9 (3.2149, 46.1978) -> (3.2149, 45.2167)
  line L10 (-2.9738, 46.1978) -> (3.2149, 46.1978)
  line L11 (-2.9738, 41.6837) -> (-2.9738, 46.1978)
  line L12 (-2.0385, 41.6837) -> (-2.9738, 41.6837)
  line L13 (-2.0385, 45.2167) -> (-2.0385, 41.6837)
  line L14 (3.2149, 45.2167) -> (-2.0385, 45.2167)
  curve K1 (-1.0914, 37.3288) -> (-0.0082, 37.0987)
  curve K2 (-1.8308, 37.954) -> (-1.0914, 37.3288)
  curve K3 (-2.0937, 38.8438) -> (-1.8308, 37.954)
  curve K4 (-1.8308, 39.7338) -> (-2.0937, 38.8438)
  curve K5 (-1.0955, 40.3593) -> (-1.8308, 39.7338)
  curve K6 (-0.0082, 40.589) -> (-1.0955, 40.3593)
  line L15 (3.2149, 40.589) -> (-0.0082, 40.589)
  line L16 (3.2149, 41.5702) -> (3.2149, 40.589)
  line L17 (-0.0082, 41.5702) -> (3.2149, 41.5702)
  curve K7 (-1.5823, 41.2192) -> (-0.0082, 41.5702)
  curve K8 (-2.6951, 40.2431) -> (-1.5823, 41.2192)
  curve K9 (-3.1025, 38.8438) -> (-2.6951, 40.2431)
  curve K10 (-2.6951, 37.4446) -> (-3.1025, 38.8438)
  curve K11 (-1.5823, 36.4686) -> (-2.6951, 37.4446)
  curve K12 (-0.0082, 36.1176) -> (-1.5823, 36.4686)
  line L18 (3.2149, 36.1176) -> (-0.0082, 36.1176)
  line L19 (3.2149, 37.0987) -> (3.2149, 36.1176)
  line L20 (-0.0082, 37.0987) -> (3.2149, 37.0987)
  line L21 (3.2149, 31.0632) -> (3.2149, 29.6919)
  line L22 (-0.0226, 34.3603) -> (3.2149, 31.0632)
  line L23 (3.2149, 34.3603) -> (-0.0226, 34.3603)
  line L24 (3.2149, 35.3415) -> (3.2149, 34.3603)
  line L25 (-2.9738, 35.3415) -> (3.2149, 35.3415)
  line L26 (-2.9738, 34.3603) -> (-2.9738, 35.3415)
  line L27 (-1.3566, 34.3603) -> (-2.9738, 34.3603)
  line L28 (-0.0165, 32.9884) -> (-1.3566, 34.3603)
  line L29 (-2.9738, 30.8239) -> (-0.0165, 32.9884)
  line L30 (-2.9738, 29.6324) -> (-2.9738, 30.8239)
  line L31 (0.6528, 32.304) -> (-2.9738, 29.6324)
  line L32 (3.2149, 29.6919) -> (0.6528, 32.304)
  line L33 (-2.0381, 23.6503) -> (-2.0381, 28.2323)
  line L34 (-2.9745, 23.6503) -> (-2.0381, 23.6503)
  line L35 (-2.9745, 29.2138) -> (-2.9745, 23.6503)
  line L36 (0.5933, 29.2138) -> (-2.9745, 29.2138)
  line L37 (0.5933, 24.8188) -> (0.5933, 29.2138)
  line L38 (-0.3431, 24.8188) -> (0.5933, 24.8188)
  line L39 (-0.3431, 28.2323) -> (-0.3431, 24.8188)
  line L40 (-2.0381, 28.2323) -> (-0.3431, 28.2323)
  curve K13 (1.0109, 22.9973) -> (2.3655, 23.1508)
  line L41 (0.8721, 22.9602) -> (1.0109, 22.9973)
  line L42 (0.8721, 22.3692) -> (0.8721, 22.9602)
  line L43 (1.0109, 22.3321) -> (0.8721, 22.3692)
  curve K14 (2.3655, 22.1787) -> (1.0109, 22.3321)
  line L44 (3.2149, 22.1787) -> (2.3655, 22.1787)
  line L45 (3.2149, 23.1508) -> (3.2149, 22.1787)
  line L46 (2.3655, 23.1508) -> (3.2149, 23.1508)
  curve K15 (0.1495, 10.6022) -> (-0.0796, 10.2291)
  curve K16 (0.3835, 10.301) -> (0.1495, 10.6022)
  curve K17 (0.8064, 9.9902) -> (0.3835, 10.301)
  curve K18 (1.473, 9.8721) -> (0.8064, 9.9902)
  curve K19 (2.869, 10.4697) -> (1.473, 9.8721)
  curve K20 (3.3436, 12.1202) -> (2.869, 10.4697)
  curve K21 (2.9575, 13.6691) -> (3.3436, 12.1202)
  curve K22 (1.7923, 14.366) -> (2.9575, 13.6691)
  line L47 (1.5805, 14.3947) -> (1.7923, 14.366)
  line L48 (1.5805, 13.3397) -> (1.5805, 14.3947)
  line L49 (1.7177, 13.3014) -> (1.5805, 13.3397)
  curve K23 (2.1756, 12.9336) -> (1.7177, 13.3014)
  curve K24 (2.3534, 12.1293) -> (2.1756, 12.9336)
  curve K25 (2.0991, 11.2103) -> (2.3534, 12.1293)
  curve K26 (1.427, 10.9085) -> (2.0991, 11.2103)
  curve K27 (0.8927, 11.0876) -> (1.427, 10.9085)
  curve K28 (0.6542, 11.5836) -> (0.8927, 11.0876)
  curve K29 (0.5928, 12.3777) -> (0.6542, 11.5836)
  line L50 (0.5928, 12.8499) -> (0.5928, 12.3777)
  line L51 (-0.3423, 12.8499) -> (0.5928, 12.8499)
  line L52 (-0.3423, 12.3503) -> (-0.3423, 12.8499)
  curve K30 (-0.5272, 11.117) -> (-0.3423, 12.3503)
  curve K31 (-1.1951, 10.7339) -> (-0.5272, 11.117)
  curve K32 (-1.8427, 11.0593) -> (-1.1951, 10.7339)
  curve K33 (-2.0937, 12.074) -> (-1.8427, 11.0593)
  curve K34 (-1.9164, 12.9736) -> (-2.0937, 12.074)
  curve K35 (-1.4675, 13.366) -> (-1.9164, 12.9736)
  line L53 (-1.3301, 13.4035) -> (-1.4675, 13.366)
  line L54 (-1.3301, 14.441) -> (-1.3301, 13.4035)
  line L55 (-1.5421, 14.4122) -> (-1.3301, 14.441)
  curve K36 (-2.7138, 13.6798) -> (-1.5421, 14.4122)
  curve K37 (-3.1025, 12.074) -> (-2.7138, 13.6798)
  curve K38 (-2.6316, 10.3367) -> (-3.1025, 12.074)
  curve K39 (-1.2503, 9.6975) -> (-2.6316, 10.3367)
  curve K40 (-0.5234, 9.8481) -> (-1.2503, 9.6975)
  curve K41 (-0.0796, 10.2291) -> (-0.5234, 9.8481)
  curve K42 (-2.0385, 6.186) -> (-1.7636, 5.2041)
  line L56 (-2.0385, 8.0505) -> (-2.0385, 6.186)
  line L57 (2.2797, 8.0505) -> (-2.0385, 8.0505)
  line L58 (2.2797, 6.186) -> (2.2797, 8.0505)
  curve K43 (2.0046, 5.2041) -> (2.2797, 6.186)
  curve K44 (1.2412, 4.517) -> (2.0046, 5.2041)
  curve K45 (0.1207, 4.2659) -> (1.2412, 4.517)
  curve K46 (-0.9999, 4.517) -> (0.1207, 4.2659)
  curve K47 (-1.7636, 5.2041) -> (-0.9999, 4.517)
  curve K48 (2.8166, 4.6653) -> (1.7085, 3.6059)
  curve K49 (3.2149, 6.186) -> (2.8166, 4.6653)
  line L59 (3.2149, 9.0316) -> (3.2149, 6.186)
  line L60 (-2.9738, 9.0316) -> (3.2149, 9.0316)
  line L61 (-2.9738, 6.186) -> (-2.9738, 9.0316)
  curve K50 (-2.5699, 4.6683) -> (-2.9738, 6.186)
  curve K51 (-1.4537, 3.6106) -> (-2.5699, 4.6683)
  curve K52 (0.1298, 3.2295) -> (-1.4537, 3.6106)
  curve K53 (1.7085, 3.6059) -> (0.1298, 3.2295)
  curve K54 (3.2228, 18.646) -> (4.0606, 17.7963)
  line L62 (3.2216, 18.646) -> (3.2228, 18.646)
  line L63 (3.2216, 19.8005) -> (3.2216, 18.646)
  line L64 (3.2194, 19.8005) -> (3.2216, 19.8005)
  curve K55 (2.246, 21.3428) -> (3.2194, 19.8005)
  curve K56 (1.4262, 21.5404) -> (2.246, 21.3428)
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extrude "Extrude3" cut sketch "Sketch4" along a picked direction blind -1
sketch "Sketch5" plane through (0, 0, 50) normal (0, 0, 1) x axis (-1, 0, 0)
  line L1 (-14.4338, 0) -> (-7.2169, 12.5)
  line L2 (-7.2169, -12.5) -> (-14.4338, 0)
  line L3 (7.2169, -12.5) -> (-7.2169, -12.5)
  line L4 (14.4338, 0) -> (7.2169, -12.5)
  line L5 (7.2169, 12.5) -> (14.4338, 0)
  line L6 (-7.2169, 12.5) -> (7.2169, 12.5)
  line L7 (-5.7735, -10) -> (-11.547, 0)
  line L8 (5.7735, -10) -> (-5.7735, -10)
  line L9 (11.547, 0) -> (5.7735, -10)
  line L10 (5.7735, 10) -> (11.547, 0)
  line L11 (-5.7735, 10) -> (5.7735, 10)
  line L12 (-11.547, 0) -> (-5.7735, 10)
  dimension "d50" = -2.5
extrude "Extrude4" cut sketch "Sketch5" profile of L7 L8 L9 L10 L11 L12 along a picked direction to an object
sketch "Sketch6" plane through (10.8253, -6.25, 0) normal (0.866, -0.5, 0) x axis (0.5, 0.866, 0)
  line L1 (7.2169, 0) -> (-7.2169, 0)
  line L2 (7.2169, 50) -> (7.2169, 0)
  line L3 (-7.2169, 50) -> (7.2169, 50)
  line L4 (-7.2169, 0) -> (-7.2169, 50)
  line L5 (7.2169, 50) -> (-7.2169, 0)
  line L6 (5, 0) -> (-5, 0)
  line L7 (5, 50) -> (5, 0)
  line L8 (-5, 50) -> (5, 50)
  line L9 (-5, 0) -> (-5, 50)
  line L10 (5, 50) -> (-5, 0)
  line L11 (-5, 50) -> (5, 0)
  line L12 (5.5, 0) -> (-5.5, 0)
  line L13 (5.5, 50) -> (5.5, 0)
  line L14 (-5.5, 50) -> (5.5, 50)
  line L15 (-5.5, 0) -> (-5.5, 50)
  line L16 (5.5, 50) -> (-5.5, 0)
  line L17 (-5.5, 50) -> (5.5, 0)
  line L18 (7.2169, 2) -> (-7.2169, 2)
  point P2 (-7.2169, 0)
  point P6 (-7.2169, 0)
  point P4 (7.2169, 50)
  point P7 (7.2169, 50)
  point P12 (0, 25)
  point P17 (0, 25)
  point P10 (5, 50)
  point P11 (-5, 50)
  point P15 (5.5, 50)
  point P16 (-5.5, 50)
  point P14 (5.5, 0)
  coincident P2 P6
  coincident P4 P7
  horizontal L6
  perpendicular L6 L7
  parallel L6 L8
  parallel L7 L9
  coincident L10 P12
  coincident L11 P12
  midpoint L5 P12
  horizontal L12
  perpendicular L12 L13
  parallel L12 L14
  parallel L13 L15
  coincident L16 P17
  coincident L17 P17
  coincident P12 P17
  dimension "d53" distance P10 P11 = 10
  dimension "d54" distance P15 P16 = 11
  dimension "d55" distance P14 P15 = 50
  dimension "d68" = -2
extrude "Extrude5" cut sketch "Sketch6" profile of L3 L5 L7 L9 L13 L14 L15 L18 along a picked direction to an object
chamfer "Chamfer1" distance 2
sketch "Sketch7" plane through (10.8253, -6.25, 0) normal (0.866, -0.5, 0) x axis (0.5, 0.866, 0)
  line L1 (5, 50) -> (5, 2)
  line L2 (-7.2169, 50) -> (-5.5, 50)
  line L3 (-5, 2) -> (-5, 50)
  line L4 (7.2169, 0) -> (-7.2169, 0)
  line L5 (-7.2169, 22.5) -> (-7.2169, 0)
  line L6 (7.2831, 22.5) -> (-7.2169, 22.5)
  line L7 (7.2831, 25.5) -> (7.2831, 22.5)
  line L8 (-7.2169, 25.5) -> (7.2831, 25.5)
  line L9 (-7.2169, 22.5) -> (-7.2169, 25.5)
  line L10 (-5.5, 50) -> (-5.5, 2)
  line L11 (-7.2169, 0) -> (-7.2169, 50)
  line L12 (7.2169, 50) -> (7.2169, 0)
  line L13 (5.5, 50) -> (7.2169, 50)
  line L14 (5.5, 2) -> (5.5, 50)
  line L15 (5, 2) -> (5.5, 2)
  line L16 (-5.5, 2) -> (-5, 2)
  line L17 (-5, 50) -> (5, 50)
  point P5 (-7.2169, 0)
  point P6 (-7.2169, 0)
  point P7 (-7.2169, 22.5)
  point P8 (7.2831, 22.5)
  point P10 (-7.2169, 25.5)
  coincident P5 P6
  perpendicular L4 L5
  horizontal L6
  vertical L7
  horizontal L8
  vertical L9
  dimension "d60" distance P6 P7 = 22.5
  dimension "d61" distance P7 P8 = 14.5
  dimension "d62" distance P7 P10 = 3
extrude "Extrude6" new body sketch "Sketch7" profile of L1 L3 L6 L8 along a picked direction blind 1.5
chamfer "Chamfer2" distance 1.5
fillet "Fillet1" radius 1
work_plane "WorkPlane1"
mirror "Mirror2" mirrorStitchTolerance 0.1
combine "Combine1"
mirror "Mirror1" mirrorStitchTolerance 0.1
mirror "Mirror1" mirrorStitchTolerance 0.1 named "d39_1"
sketch "Sketch1" plane through (0, 0, 0) normal (0, 0, 1) x axis (1, 0, 0)
  line L1 (37.5278, 105) -> (-17.3205, 10)
  line L2 (90, 10) -> (-17.3205, 10)
  line L3 (117.5278, 105) -> (37.5278, 105)
  line L4 (15.1099, -13.1031) -> (117.5278, 105)
  line L5 (44.2265, 70) -> (47.1132, 75)
  line L6 (47.1132, 65) -> (44.2265, 70)
  line L7 (52.8868, 65) -> (47.1132, 65)
  line L8 (55.7735, 70) -> (52.8868, 65)
  line L9 (52.8868, 75) -> (55.7735, 70)
  line L10 (47.1132, 75) -> (52.8868, 75)
  line L11 (54.3301, 72.5) -> (50, 70)
  line L12 (54.3301, 67.5) -> (50, 70)
  line L13 (-19.6944, 13.5714) -> (-22.5812, 18.5714)
  line L14 (-13.9209, 13.5714) -> (-19.6944, 13.5714)
  line L15 (-11.0342, 18.5714) -> (-13.9209, 13.5714)
  line L16 (-13.9209, 23.5714) -> (-11.0342, 18.5714)
  line L17 (-22.5812, 18.5714) -> (-19.6944, 23.5714)
  line L18 (-19.6944, 23.5714) -> (-13.9209, 23.5714)
  line L19 (-8.5598, 20) -> (-11.4466, 25)
  line L20 (-2.7863, 20) -> (-8.5598, 20)
  line L21 (0.1004, 25) -> (-2.7863, 20)
  line L22 (-2.7863, 30) -> (0.1004, 25)
  line L23 (-11.4466, 25) -> (-8.5598, 30)
  line L24 (-8.5598, 30) -> (-2.7863, 30)
  line L25 (2.5748, 13.5714) -> (-0.312, 18.5714)
  line L26 (8.3483, 13.5714) -> (2.5748, 13.5714)
  line L27 (11.2351, 18.5714) -> (8.3483, 13.5714)
  line L28 (8.3483, 23.5714) -> (11.2351, 18.5714)
  line L29 (-0.312, 18.5714) -> (2.5748, 23.5714)
  line L30 (2.5748, 23.5714) -> (8.3483, 23.5714)
  line L31 (-8.5598, 32.8571) -> (-11.4466, 37.8571)
  line L32 (-2.7863, 32.8571) -> (-8.5598, 32.8571)
  line L33 (0.1004, 37.8571) -> (-2.7863, 32.8571)
  line L34 (-2.7863, 42.8571) -> (0.1004, 37.8571)
  line L35 (-11.4466, 37.8571) -> (-8.5598, 42.8571)
  line L36 (-8.5598, 42.8571) -> (-2.7863, 42.8571)
  line L37 (2.5748, 26.4286) -> (-0.312, 31.4286)
  line L38 (8.3483, 26.4286) -> (2.5748, 26.4286)
  line L39 (11.2351, 31.4286) -> (8.3483, 26.4286)
  line L40 (8.3483, 36.4286) -> (11.2351, 31.4286)
  line L41 (-0.312, 31.4286) -> (2.5748, 36.4286)
  line L42 (2.5748, 36.4286) -> (8.3483, 36.4286)
  line L43 (13.7094, 20) -> (10.8227, 25)
  line L44 (19.4829, 20) -> (13.7094, 20)
  line L45 (22.3697, 25) -> (19.4829, 20)
  line L46 (19.4829, 30) -> (22.3697, 25)
  line L47 (10.8227, 25) -> (13.7094, 30)
  line L48 (13.7094, 30) -> (19.4829, 30)
  line L49 (2.5748, 39.2857) -> (-0.312, 44.2857)
  line L50 (8.3483, 39.2857) -> (2.5748, 39.2857)
  line L51 (11.2351, 44.2857) -> (8.3483, 39.2857)
  line L52 (8.3483, 49.2857) -> (11.2351, 44.2857)
  line L53 (-0.312, 44.2857) -> (2.5748, 49.2857)
  line L54 (2.5748, 49.2857) -> (8.3483, 49.2857)
  line L55 (13.7094, 32.8571) -> (10.8227, 37.8571)
  line L56 (19.4829, 32.8571) -> (13.7094, 32.8571)
  line L57 (22.3697, 37.8571) -> (19.4829, 32.8571)
  line L58 (19.4829, 42.8571) -> (22.3697, 37.8571)
  line L59 (10.8227, 37.8571) -> (13.7094, 42.8571)
  line L60 (13.7094, 42.8571) -> (19.4829, 42.8571)
  line L61 (24.844, 26.4286) -> (21.9573, 31.4286)
  line L62 (30.6175, 26.4286) -> (24.844, 26.4286)
  line L63 (33.5043, 31.4286) -> (30.6175, 26.4286)
  line L64 (30.6175, 36.4286) -> (33.5043, 31.4286)
  line L65 (21.9573, 31.4286) -> (24.844, 36.4286)
  line L66 (24.844, 36.4286) -> (30.6175, 36.4286)
  line L67 (2.5748, 52.1429) -> (-0.312, 57.1429)
  line L68 (8.3483, 52.1429) -> (2.5748, 52.1429)
  line L69 (11.2351, 57.1429) -> (8.3483, 52.1429)
  line L70 (8.3483, 62.1429) -> (11.2351, 57.1429)
  line L71 (-0.312, 57.1429) -> (2.5748, 62.1429)
  line L72 (2.5748, 62.1429) -> (8.3483, 62.1429)
  line L73 (13.7094, 45.7143) -> (10.8227, 50.7143)
  line L74 (19.4829, 45.7143) -> (13.7094, 45.7143)
  line L75 (22.3697, 50.7143) -> (19.4829, 45.7143)
  line L76 (19.4829, 55.7143) -> (22.3697, 50.7143)
  line L77 (10.8227, 50.7143) -> (13.7094, 55.7143)
  line L78 (13.7094, 55.7143) -> (19.4829, 55.7143)
  line L79 (24.844, 39.2857) -> (21.9573, 44.2857)
  line L80 (30.6175, 39.2857) -> (24.844, 39.2857)
  line L81 (33.5043, 44.2857) -> (30.6175, 39.2857)
  line L82 (30.6175, 49.2857) -> (33.5043, 44.2857)
  line L83 (21.9573, 44.2857) -> (24.844, 49.2857)
  line L84 (24.844, 49.2857) -> (30.6175, 49.2857)
  line L85 (35.9786, 32.8571) -> (33.0919, 37.8571)
  line L86 (41.7521, 32.8571) -> (35.9786, 32.8571)
  line L87 (44.6389, 37.8571) -> (41.7521, 32.8571)
  line L88 (41.7521, 42.8571) -> (44.6389, 37.8571)
  line L89 (33.0919, 37.8571) -> (35.9786, 42.8571)
  line L90 (35.9786, 42.8571) -> (41.7521, 42.8571)
  line L91 (13.7094, 58.5714) -> (10.8227, 63.5714)
  line L92 (19.4829, 58.5714) -> (13.7094, 58.5714)
  line L93 (22.3697, 63.5714) -> (19.4829, 58.5714)
  line L94 (19.4829, 68.5714) -> (22.3697, 63.5714)
  line L95 (10.8227, 63.5714) -> (13.7094, 68.5714)
  line L96 (13.7094, 68.5714) -> (19.4829, 68.5714)
  line L97 (24.844, 52.1429) -> (21.9573, 57.1429)
  line L98 (30.6175, 52.1429) -> (24.844, 52.1429)
  line L99 (33.5043, 57.1429) -> (30.6175, 52.1429)
  line L100 (30.6175, 62.1429) -> (33.5043, 57.1429)
  line L101 (21.9573, 57.1429) -> (24.844, 62.1429)
  line L102 (24.844, 62.1429) -> (30.6175, 62.1429)
  line L103 (35.9786, 45.7143) -> (33.0919, 50.7143)
  line L104 (41.7521, 45.7143) -> (35.9786, 45.7143)
  line L105 (44.6389, 50.7143) -> (41.7521, 45.7143)
  line L106 (41.7521, 55.7143) -> (44.6389, 50.7143)
  line L107 (33.0919, 50.7143) -> (35.9786, 55.7143)
  line L108 (35.9786, 55.7143) -> (41.7521, 55.7143)
  line L109 (47.1132, 39.2857) -> (44.2265, 44.2857)
  line L110 (52.8868, 39.2857) -> (47.1132, 39.2857)
  line L111 (55.7735, 44.2857) -> (52.8868, 39.2857)
  line L112 (52.8868, 49.2857) -> (55.7735, 44.2857)
  line L113 (44.2265, 44.2857) -> (47.1132, 49.2857)
  line L114 (47.1132, 49.2857) -> (52.8868, 49.2857)
  line L115 (13.7094, 71.4286) -> (10.8227, 76.4286)
  line L116 (19.4829, 71.4286) -> (13.7094, 71.4286)
  line L117 (22.3697, 76.4286) -> (19.4829, 71.4286)
  line L118 (19.4829, 81.4286) -> (22.3697, 76.4286)
  line L119 (10.8227, 76.4286) -> (13.7094, 81.4286)
  line L120 (13.7094, 81.4286) -> (19.4829, 81.4286)
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  point P1 (0, 0)
  point P2 (0, 0)
  point P8 (50, 70)
  point P15 (50, 70)
  point P16 (50, 70)
  point P17 (54.3301, 72.5)
  point P18 (50, 70)
  point P19 (54.3301, 67.5)
  point P384 (0, 0)
  point P5 (37.5278, 105)
  point P6 (117.5278, 105)
  coincident P1 P2
  horizontal L2
  coincident P8 P15
  coincident P15 P16
  midpoint L9 P17
  coincident P8 P18
  midpoint L8 P19
  coincident P1 P384
  dimension "d1_1_1" diameter = 40
  dimension "d2_1_1" angle L1 L2 = 60
  dimension "d4_1_1" distance P5 P6 = 80
  dimension "d6_1_1" distance P15 L10 = 5
  dimension "d11_1_1" = 3
  dimension "d12_1_1" distance = 13
  dimension "d9_1_1" R-Pattern1-uDistance = 90
  dimension "d10_1_1" R-Pattern1-vDistance = 90
extrude "Extrude1" new body sketch "Sketch1" along normal blind 5 named "d13_1_1"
